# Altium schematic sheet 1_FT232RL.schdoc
size 429 x 307 mm; Symbol: Drawing-Symbol_A4; Device: Drawing-Symbol_A4; @Project Name: Slowpoke_Adapter; @Page Count: 1; @Update Date: 2025-12-08; @Create Date: 2025-12-07; @Schematic Name: Schematic4; @Page No: 1; @Page Name: FT232RL; Company: EasyEDA.com; Version: V1.0; Page Size: A4; @Create Time: 06:32:35; @Update Time: 21:45:33; Width: 1655; Height: 1170; Region Start: 1; X Region Count: 6; Y Region Count: 4; Blade Width: 10; Title Block Position: 3; @Board Name: FT232
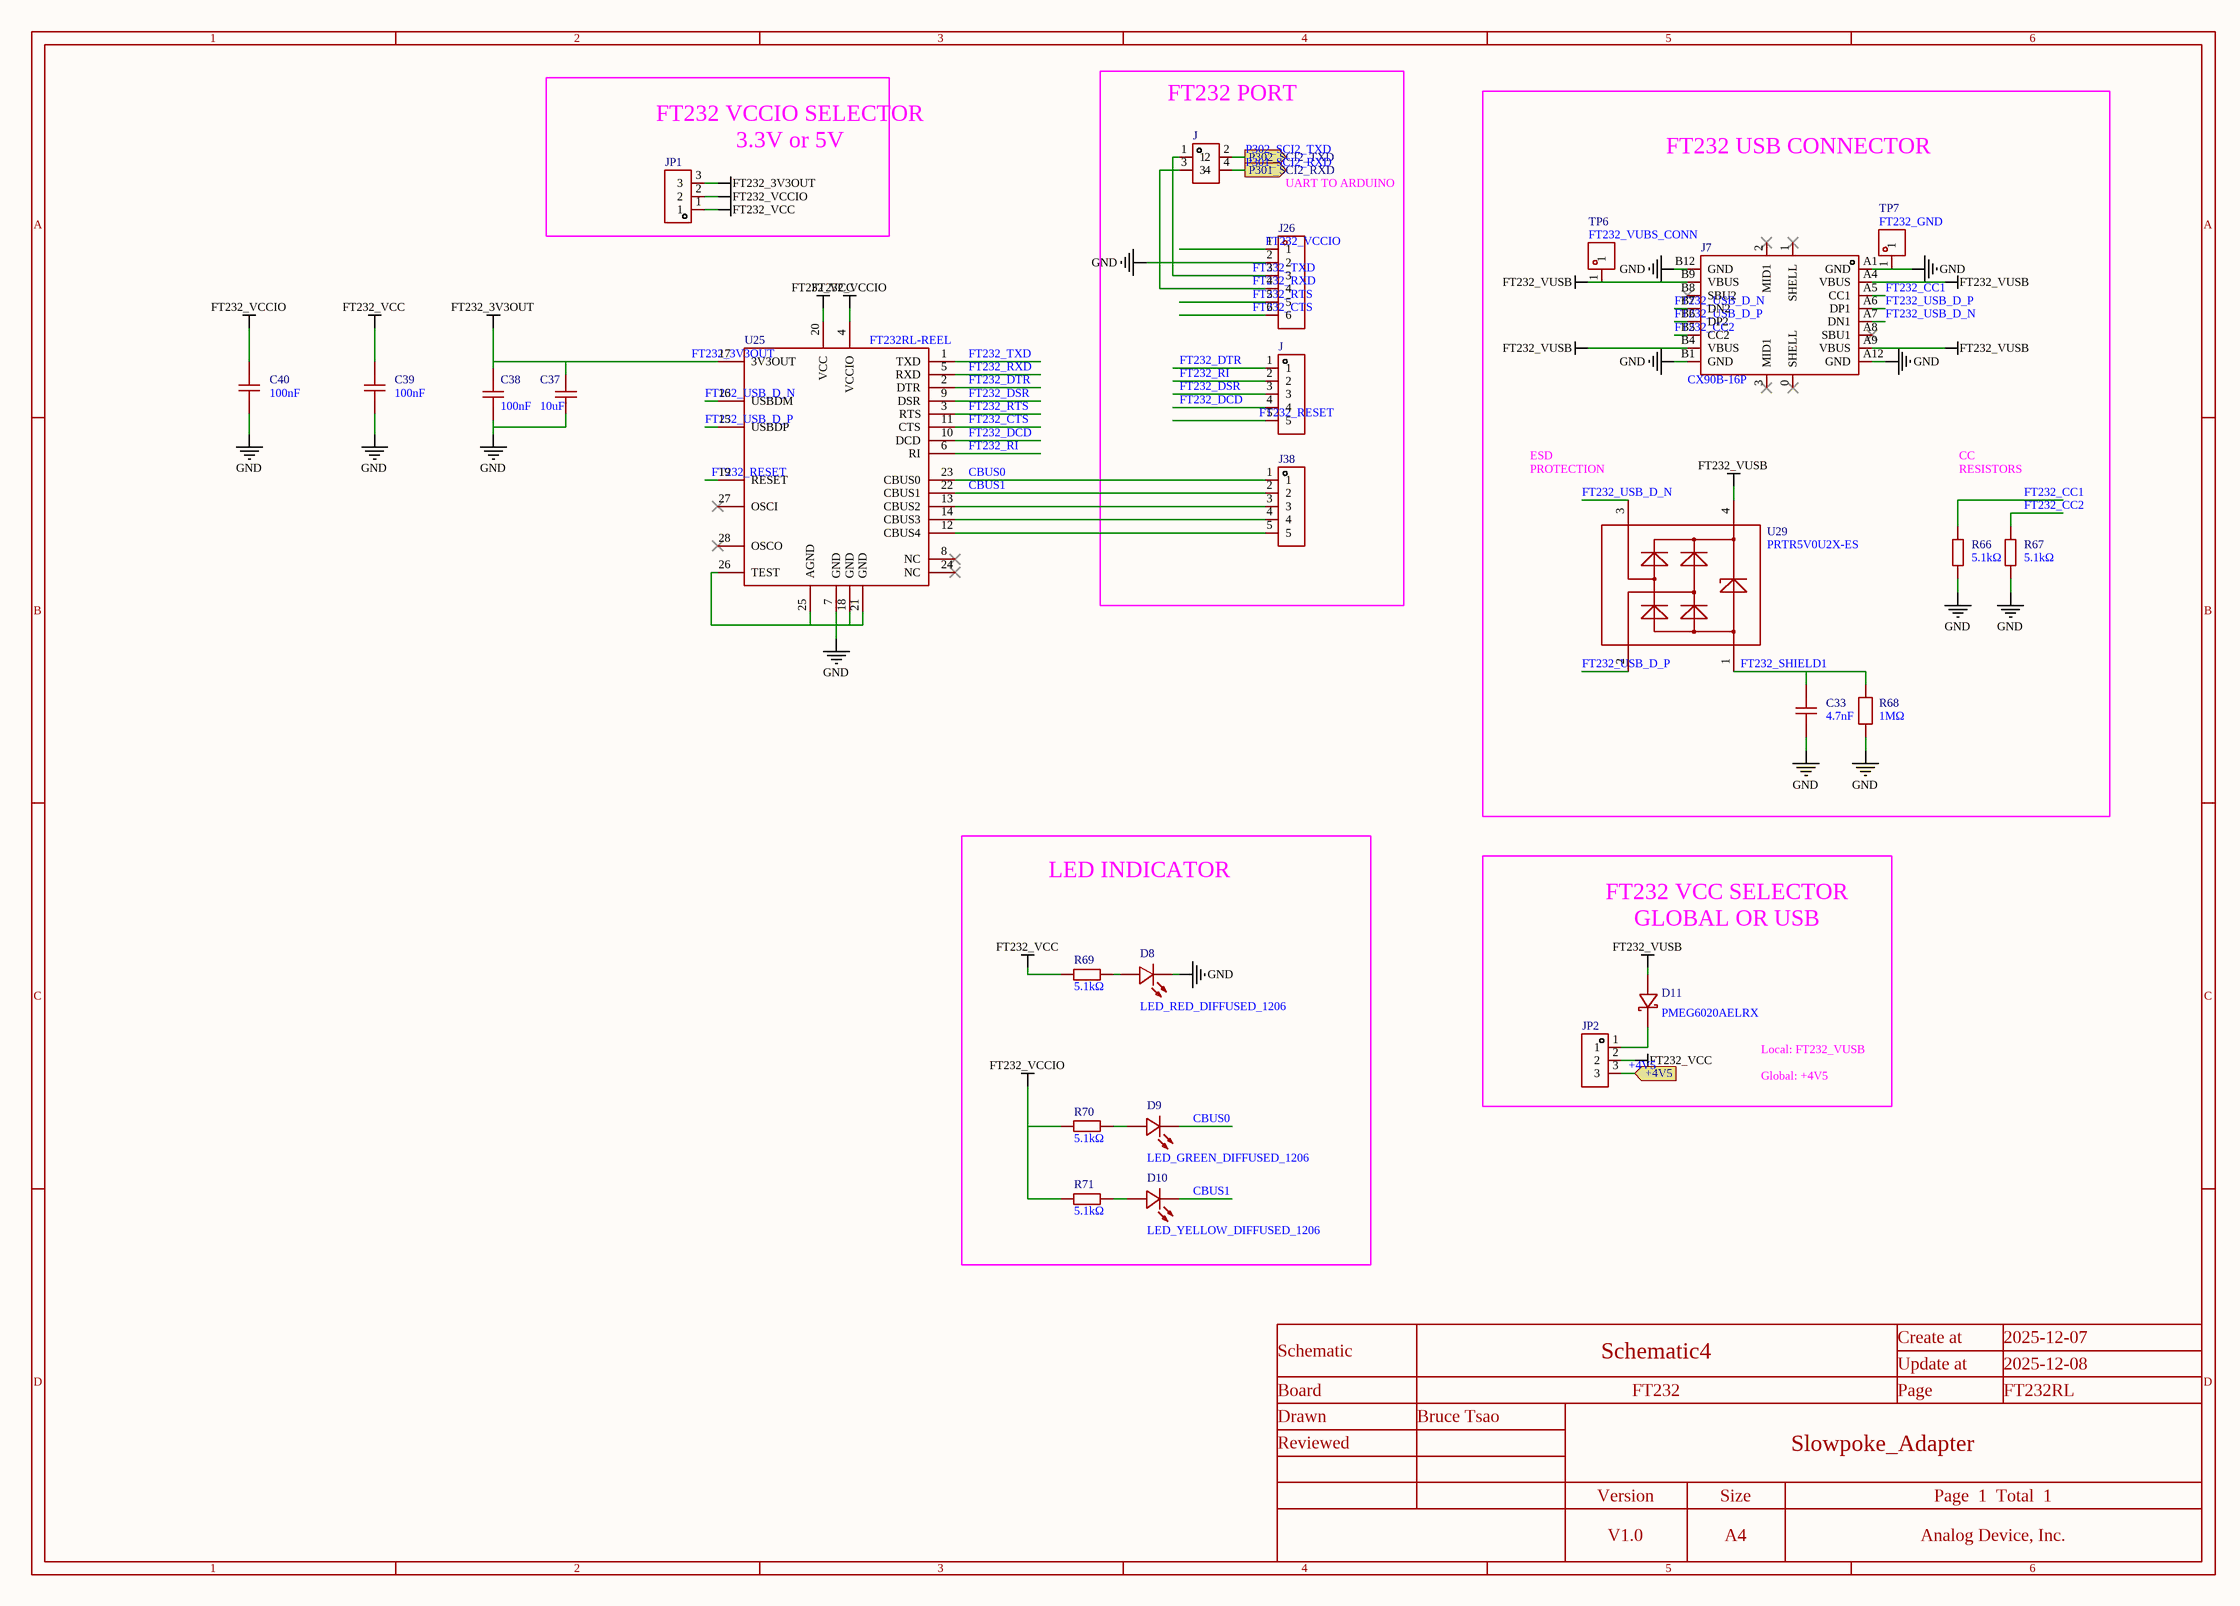
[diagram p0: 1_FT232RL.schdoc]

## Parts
(Parts that share a designator on the sheet are numbered #1, #2 ... from top to bottom, then left to right.)
C33  4.7nF  [C0805]
C37  10uF  [C0402]
C38  100nF  [C0402]
C39  100nF  [C0402]
C40  100nF  [C0402]
D8  LED_RED_DIFFUSED_1206  [LED1206-RD]
D9  LED_GREEN_DIFFUSED_1206  [LED1206-RD]
D10  LED_YELLOW_DIFFUSED_1206  [LED1206-RD]
D11  PMEG6020AELRX  [SOD-123_L2.6-W1.7-LS3.5-RD]
J7  CX90B-16P  [USB-C-SMD_CX90B-16P]
J26  2.54-1*6P母  [HDR-TH_6P-P2.54-V-F]  (value not drawn)
J38  PZ254V-11-05P  [HDR-TH_5P-P2.54-V-M]  (value not drawn)
J#1  ZX-PZ2.54-2-2PZZ  [HDR-TH_4P-P2.54-V-M-R2-C2-S2.54]  (value not drawn)
J#2  PZ254V-11-05P  [HDR-TH_5P-P2.54-V-M]  (value not drawn)
JP1  PZ254V-11-03P  [HDR-TH_3P-P2.54-V-M]  (value not drawn)
JP2  PZ254V-11-03P  [HDR-TH_3P-P2.54-V-M]  (value not drawn)
R66  5.1kΩ  [R0402]
R67  5.1kΩ  [R0402]
R68  1MΩ  [R0402]
R69  5.1kΩ  [R0402]
R70  5.1kΩ  [R0402]
R71  5.1kΩ  [R0402]
TP6  FT232_VUBS_CONN  [TESTPOINT-TH_BD3.2]
TP7  FT232_GND  [TESTPOINT-TH_BD3.2]
U25  FT232RL-REEL  [SSOP-28_L10.2-W5.3-P0.65-LS7.8-BL]
U29  PRTR5V0U2X-ES  [SOT-143_L2.9-W1.3-P1.92-LS2.3-BR]

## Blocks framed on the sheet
FT232 PORT: J26 J38 J#1 J#2
FT232 USB CONNECTOR: C33 J7 R66-R68 TP6 TP7 U29
LED INDICATOR: D8-D10 R69-R71

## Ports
+4V5 (in), P301_SCI2_RXD (out), P302_SCI2_TXD (out)

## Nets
FT232_3V3OUT: C37.2 C38.2 JP1.3 U25.17(3V3OUT)
FT232_VCC: C39.1 JP1.1 JP2.2 R69.2 U25.20(VCC)
FT232_VCCIO: C40.1 J26.1 JP1.2 R70.2 R71.2 U25.4(VCCIO)
FT232_VUSB: D11.2(+) J7.A4(VBUS) J7.A9(VBUS) J7.B4(VBUS) J7.B9(VBUS) TP6.1 U29.4(VCC)
GND: C33.1 C37.1 C38.1 C39.2 C40.2 D8.1(K) J7.A1(GND) J7.A12(GND) J7.B1(GND) J7.B12(GND) J26.2 R66.1 R67.1 R68.1 TP7.1 U25.7(GND) U25.18(GND) U25.21(GND) U25.25(AGND) U25.26(TEST)
+4V5: JP2.3 ; port +4V5
CBUS0: D9.1(K) J38.1 U25.23(CBUS0)
CBUS1: D10.1(K) J38.2 U25.22(CBUS1)
FT232_CC1: J7.A5(CC1) R66.2
FT232_CC2: J7.B5(CC2) R67.2
FT232_CTS: J26.6 U25.11(CTS)
FT232_DCD: J#2.4 U25.10(DCD)
FT232_DSR: J#2.3 U25.9(DSR)
FT232_DTR: J#2.1 U25.2(DTR)
FT232_RESET: J#2.5 U25.19(RESET)
FT232_RI: J#2.2 U25.6(RI)
FT232_RTS: J26.5 U25.3(RTS)
FT232_RXD: J26.4 J#1.3 U25.5(RXD)
FT232_SHIELD1: C33.2 R68.2 U29.1(GND)
FT232_TXD: J26.3 J#1.1 U25.1(TXD)
FT232_USB_D_N: J7.A7(DN1) J7.B7(DN2) U25.16(USBDM) U29.3(IO)
FT232_USB_D_P: J7.A6(DP1) J7.B6(DP2) U25.15(USBDP) U29.2(IO)
P301_SCI2_RXD: J#1.4 ; port P301_SCI2_RXD
P302_SCI2_TXD: J#1.2 ; port P302_SCI2_TXD
NetD8_2: D8.2(A) R69.1
NetD9_2: D9.2(A) R70.1
NetD10_2: D10.2(A) R71.1
NetD11_1: D11.1(-) JP2.1
NetJ38_3: J38.3 U25.13(CBUS2)
NetJ38_4: J38.4 U25.14(CBUS3)
NetJ38_5: J38.5 U25.12(CBUS4)

Not connected (* = marked no-connect by the designer): J7 0(SHELL)* 1(SHELL)* 2(MID1)* 3(MID1)* A8(SBU1)* B8(SBU2)*; U25 8(NC)* 24(NC)* 27(OSCI)* 28(OSCO)*

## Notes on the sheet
- (near JP1) FT232 VCCIO SELECTOR
  3.3V or 5V
- UART TO ARDUINO
- (near U29) ESD
  PROTECTION
- CC
  RESISTORS
- (near D11) FT232 VCC SELECTOR
  GLOBAL OR USB
- Local: FT232_VUSB
  Global: +4V5

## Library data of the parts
C33 = FV21X472K102ECG: Manufacturer: PSA(信昌电陶); Add into BOM: yes; Tolerance: ±10%; Voltage Rating: 1kV; Temperature Coefficient: X7R
C37 = CL05A105KP5NNNC: Manufacturer: SAMSUNG(三星); Add into BOM: yes; Tolerance: ±10%; Voltage Rating: 10V; Temperature Coefficient: X5R
C38-C40 = GRM155R61H104KE19D: Manufacturer: muRata(村田); Add into BOM: yes; Tolerance: ±10%
D8-D10 = LTST-C150KRKT: Manufacturer: LITEON(光宝); Add into BOM: yes; Emitted Color: Red; Forward Voltage (VF): 2V; Power Dissipation: 62.5mW; Forward Current: 20mA; Dominant Wavelength: 624nm; Peak Wavelength: 639nm; Lens Color: 无色透明透镜; Luminous Intensity: 54mcd; Viewing Angle: 130°
D11 = PMEG6020AELRX: Manufacturer: Nexperia(安世); Add into BOM: yes; Forward Voltage (Vf@If): 670mV@2A; Reverse Voltage (Vr): 60V; Average Rectified Current (Io): 2A; Reverse Leakage Current (Ir): 700nA@60V
J7 = CX90B-16P: Manufacturer: HRS(广濑); Add into BOM: yes
J26 = 2.54-1*6P母: Manufacturer: BOOMELE(博穆精密); Symbol: Header-Female-2.54_1x6; Add into BOM: yes; Holes Structure: 1x6P; Pitch: 2.54mm; Circular Hole / Square Hole: Square Hole; Number of Positions: 6P; Current Rating: 3A; Holes Direction: Top
J38 J#2 = PZ254V-11-05P: Manufacturer: XFCN(兴飞); Add into BOM: yes; Pin Structure: 1x5P; Pitch: 2.54mm; Circluar Pins/Square Pins: Policy
J#1 = ZX-PZ2.54-2-2PZZ: Manufacturer: Megastar(兆星); Add into BOM: yes; Pin Structure: 2x2P; Pitch: 2.54mm; Circluar Pins/Square Pins: Policy; Current Rating: 3A; Voltage Rating (Max): 1kV
JP1 JP2 = PZ254V-11-03P: Manufacturer: XFCN(兴飞); Symbol: PZ254V-11-03P_C2937625; Add into BOM: yes; Pin Structure: 1x3P; Pitch: 2.54mm; Circluar Pins/Square Pins: Pin Header; Current Rating: 3A; Voltage Rating (Max): 250V
R66 R67 R69-R71 = RC0402FR-075K1L: Manufacturer: YAGEO(国巨); Add into BOM: yes; Tolerance: ±1%; Power(Watts): 62.5mW; Voltage-Supply(Max): 50V; Temperature Coefficient: ±100ppm/℃
R68 = CRCW04021M00FKED: Manufacturer: VISHAY(威世); Add into BOM: yes; Tolerance: ±1%; Power(Watts): 63mW; Voltage-Supply(Max): 50V; Temperature Coefficient: ±100ppm/℃
TP6 TP7 = RH-5011: Manufacturer: 荣和; Add into BOM: yes; Connector Type: Pin type (through board); Plastic Color: Black
U25 = FT232RL-REEL: Manufacturer: FTDI(飞特帝亚); Add into BOM: yes; Applications Function: USB to UART; USB Protocol: USB 2.0; Voltage - Supply: 3.3V~5.25V; Data Rate: 3Mbps; Current - Supply: 15mA; Supply Current (Iq): 70uA
U29 = PRTR5V0U2X-ES: Manufacturer: ElecSuper(静芯); Add into BOM: yes; Polarity: Unidirectional; Reverse Stand-Off Voltage (Vrwm): 5V; Clamping Voltage: 18V; Peak Pulse Current (Ipp): 9A@8/20us; Peak Pulse Power Dissipation (Ppp): 180W@8/20us; Voltage - Breakdown: 6V; Reverse Leakage Current (Ir): 1uA; Number of Channels: 2; level of protection: IEC 61000-4-2；IEC 61000-4-4；IEC 61000-4-5; Junction Capacitance: 0.8pF；1.6pF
